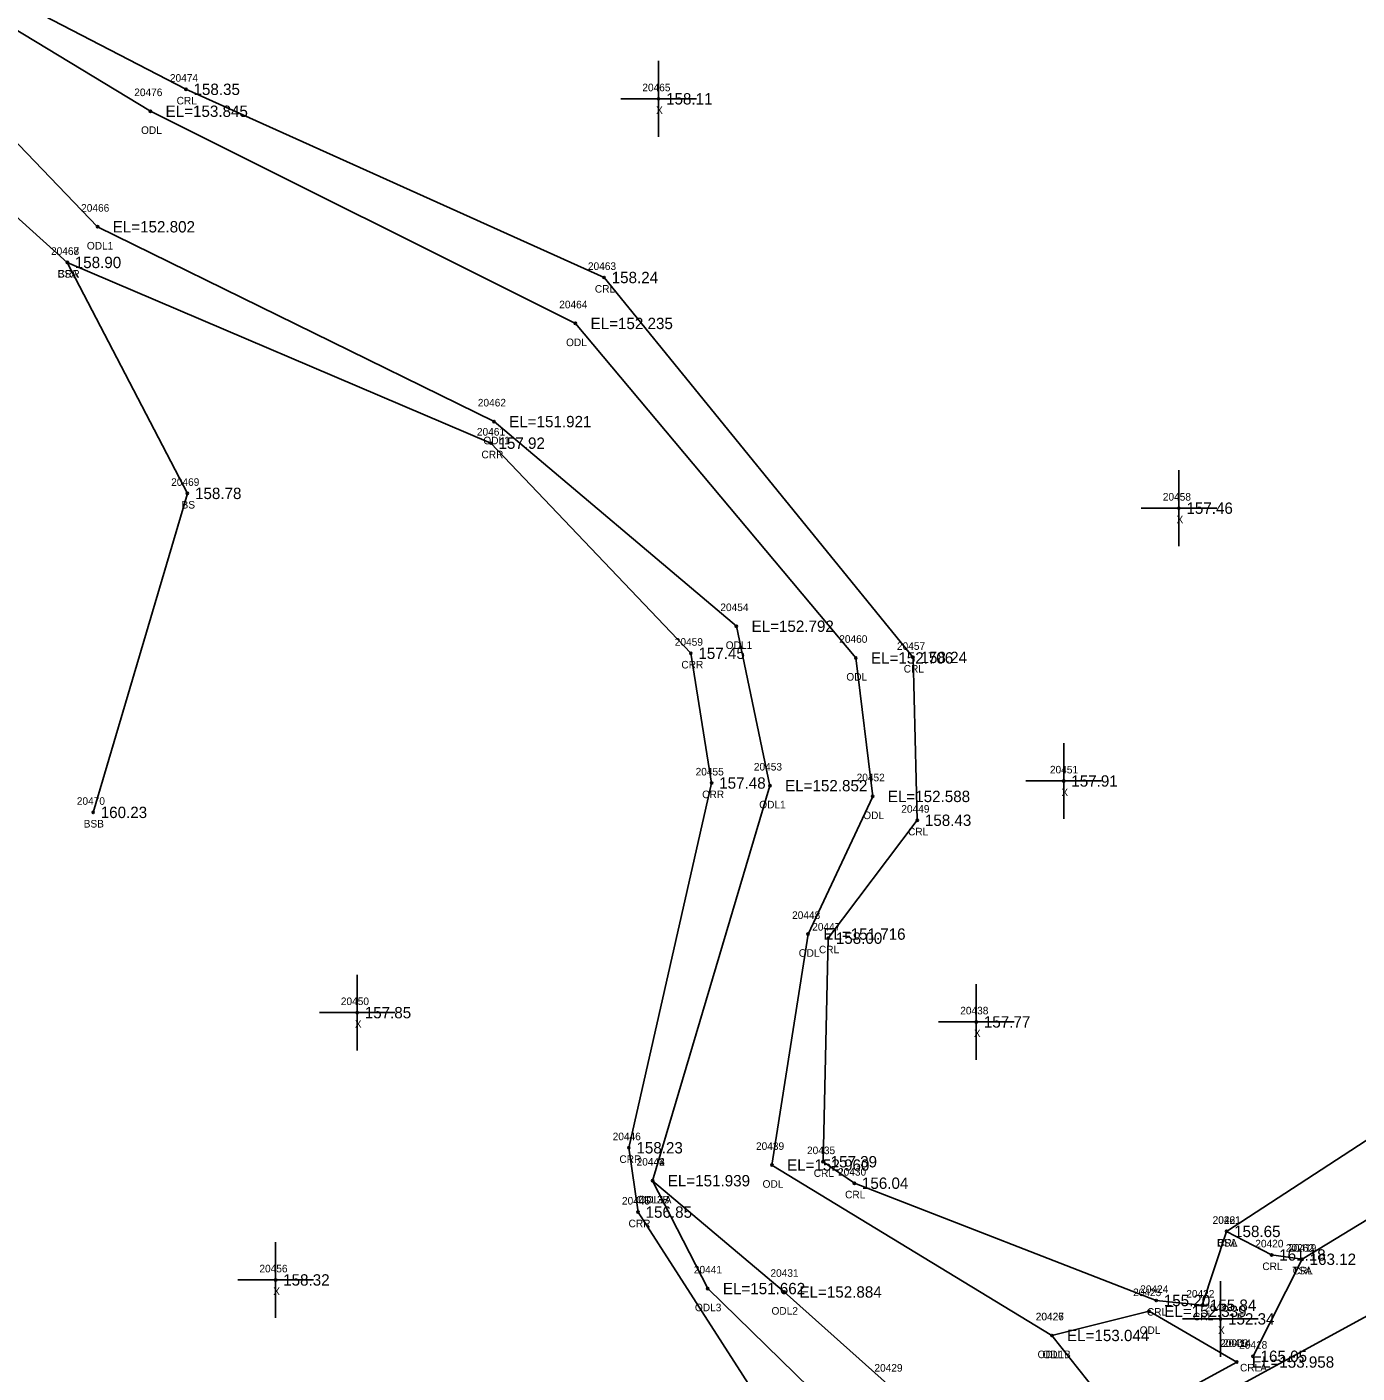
# Model space of a CAD drawing. Extents: x 2279528 to 2280976, y 1061373 to 1062235.
# Drawn here: x 2280085.6 to 2280261.4, y 1061818 to 1061995.9 of the extents above; entities that cross this region are included whole.
import ezdxf

# ---------------------------------------------------------------- set-up
doc = ezdxf.new("R2010")
doc.units = 0
for name, color, linetype in [('RD_DTM_BkLn2', 7, 'Continuous'), ('RD_DTM_BkLn_txCode', 7, 'Continuous'), ('RD_EX_H2O', 7, 'Continuous'), ('RD_EX_H2O_txCode', 7, 'Continuous'), ('RD_EX_Misc', 7, 'Continuous'), ('RD_EX_Misc_txCode', 7, 'Continuous'), ('RD_EX_Road', 7, 'Continuous'), ('RD_EX_TX_H2O_ELEV', 7, 'Continuous'), ('RD_EX_TX_Misc_ELEV', 7, 'Continuous'), ('RD_SMD_Locator', 7, 'Continuous')]:
    doc.layers.add(name, color=color, linetype=linetype)

msp = doc.modelspace()

# ---------------------------------------------------------------- linework, layer by layer
at = {"layer": 'RD_DTM_BkLn2'}
for points in [[(2280244.17, 1061836.72), (2280279.92, 1061859.99), (2280384.06, 1061910.85), (2280474.95, 1061958.02), (2280563.04, 1062001.93), (2280638.18, 1062044.64), (2280638.45, 1062052), (2280636.3, 1062090.14)], [(2280254.15, 1061833.04), (2280297.35, 1061859.31), (2280389.94, 1061901.4), (2280479.75, 1061950.78), (2280565.23, 1061997.82), (2280647.02, 1062043.23), (2280646.04, 1062059.26), (2280636.3, 1062090.14)], [(2280090.97, 1061964.76), (2280106.86, 1061934.24), (2280094.4, 1061892.09)]]:
    msp.add_lwpolyline(points, dxfattribs=at)
at = {"layer": 'RD_EX_H2O'}
msp.add_line((2280230.44, 1061811.21), (2280221.09, 1061822.97), dxfattribs=at)
for points in [[(2280211.16, 1061800.79), (2280200.18, 1061802.95), (2280195.55, 1061801.16), (2280185.62, 1061809.36), (2280166.4, 1061839.27), (2280165.19, 1061847.77), (2280176.13, 1061895.97), (2280173.38, 1061913.11), (2280146.96, 1061940.88), (2280090.97, 1061964.76), (2280049.27, 1062002.4), (2280058.65, 1062048.88), (2280050.78, 1062064.28), (2280035.9, 1062083.09), (2280001.73, 1062095.49), (2279975.65, 1062129.45), (2279976.82, 1062173.44)], [(2280168.33, 1061843.42), (2280183.83, 1061895.62), (2280179.4, 1061916.69), (2280147.37, 1061943.73), (2280094.98, 1061969.47), (2280057.58, 1062008.45), (2280067.95, 1062052.6), (2280055.34, 1062070.59), (2280037.3, 1062087.39), (2280003.55, 1062098.15), (2279979.87, 1062130.72), (2279980.65, 1062169.39)], [(2280245.52, 1061819.46), (2280233.94, 1061826.17), (2280221.09, 1061822.97), (2280184.1, 1061845.49), (2280188.88, 1061876.01), (2280197.41, 1061894.2), (2280195.18, 1061912.5), (2280158.13, 1061956.7), (2280101.97, 1061984.74), (2280076.14, 1062000.42), (2280073.45, 1062020.04), (2280088.34, 1062054.57), (2280063.06, 1062089.79), (2280022.01, 1062117.09), (2280004.42, 1062121.87), (2279996.3, 1062161.48)], [(2280247.67, 1061820.22), (2280254.15, 1061833.04), (2280250.13, 1061833.61), (2280244.17, 1061836.72), (2280240.97, 1061826.97), (2280234.88, 1061827.59), (2280194.99, 1061843.09), (2280190.85, 1061845.93), (2280191.54, 1061875.47), (2280203.31, 1061891.05), (2280202.74, 1061912.57), (2280161.92, 1061962.77), (2280106.66, 1061987.64), (2280081.48, 1062000.69), (2280077.59, 1062019.21), (2280091.23, 1062055.4), (2280068.77, 1062094.03), (2280025.87, 1062122.57), (2280008.58, 1062126.75), (2280003.39, 1062153.96)], [(2280211.72, 1061801.11), (2280200.63, 1061804.74), (2280175.61, 1061829.17), (2280168.33, 1061843.42)], [(2280227.06, 1061809.78), (2280213.62, 1061812.44), (2280199.76, 1061816.19), (2280185.73, 1061828.72), (2280168.33, 1061843.42)], [(2280211.72, 1061801.11), (2280227.06, 1061809.78), (2280230.44, 1061811.21), (2280245.52, 1061819.46)]]:
    msp.add_lwpolyline(points, dxfattribs=at)
at = {"layer": 'RD_EX_Misc'}
for p, q in [((2280169.11, 1061981.38), (2280169.11, 1061991.38)), ((2280164.11, 1061986.38), (2280174.11, 1061986.38)), ((2280237.87, 1061927.29), (2280237.87, 1061937.29)), ((2280232.87, 1061932.29), (2280242.87, 1061932.29)), ((2280222.66, 1061891.24), (2280222.66, 1061901.24)), ((2280217.66, 1061896.24), (2280227.66, 1061896.24)), ((2280129.29, 1061860.63), (2280129.29, 1061870.63)), ((2280211.1, 1061859.4), (2280211.1, 1061869.4)), ((2280124.29, 1061865.63), (2280134.29, 1061865.63)), ((2280206.1, 1061864.4), (2280216.1, 1061864.4)), ((2280118.51, 1061825.31), (2280118.51, 1061835.31)), ((2280113.51, 1061830.31), (2280123.51, 1061830.31)), ((2280243.37, 1061820.16), (2280243.37, 1061830.16)), ((2280238.37, 1061825.16), (2280248.37, 1061825.16))]:
    msp.add_line(p, q, dxfattribs=at)
at = {"layer": 'RD_EX_Road'}
msp.add_lwpolyline([(2279554.31, 1061441.46), (2279636.61, 1061486.51), (2279673.46, 1061506.76), (2279683.06, 1061512.21), (2279723.14, 1061533.54), (2279809.28, 1061580.29), (2279896.91, 1061627.91), (2279977.07, 1061671.02), (2280059.64, 1061715.57), (2280142.91, 1061760.72), (2280228.83, 1061807.06), (2280306.04, 1061849.18), (2280392.98, 1061896.71), (2280482.82, 1061945.75), (2280567.83, 1061991.78), (2280649.94, 1062036.55), (2280660.56, 1062042.19), (2280676.12, 1062050.66), (2280737.28, 1062083.64), (2280828.54, 1062132.77), (2280887.86, 1062164.61), (2280934.91, 1062190.9)], dxfattribs=at)
at = {"layer": 'RD_SMD_Locator'}
for centre in [(2280106.66, 1061987.64), (2280101.97, 1061984.74), (2280169.11, 1061986.38), (2280094.98, 1061969.47), (2280090.97, 1061964.76), (2280090.97, 1061964.76), (2280161.92, 1061962.77), (2280158.13, 1061956.7), (2280147.37, 1061943.73), (2280146.96, 1061940.88), (2280106.86, 1061934.24), (2280237.87, 1061932.29), (2280179.4, 1061916.69), (2280173.38, 1061913.11), (2280195.18, 1061912.5), (2280202.74, 1061912.57), (2280176.13, 1061895.97), (2280222.66, 1061896.24), (2280183.83, 1061895.62), (2280197.41, 1061894.2), (2280094.4, 1061892.09), (2280203.31, 1061891.05), (2280188.88, 1061876.01), (2280191.54, 1061875.47), (2280129.29, 1061865.63), (2280211.1, 1061864.4), (2280165.19, 1061847.77), (2280184.1, 1061845.49), (2280190.85, 1061845.93), (2280168.33, 1061843.42), (2280168.33, 1061843.42), (2280168.33, 1061843.42), (2280194.99, 1061843.09), (2280166.4, 1061839.27), (2280244.17, 1061836.72), (2280244.17, 1061836.72), (2280250.13, 1061833.61), (2280254.15, 1061833.04), (2280254.15, 1061833.04), (2280118.51, 1061830.31), (2280175.61, 1061829.17), (2280185.73, 1061828.72), (2280234.88, 1061827.59), (2280240.97, 1061826.97), (2280233.94, 1061826.17), (2280243.37, 1061825.16), (2280221.09, 1061822.97), (2280221.09, 1061822.97), (2280245.52, 1061819.46), (2280245.52, 1061819.46), (2280247.67, 1061820.22)]:
    msp.add_circle(centre, 0.15, dxfattribs=at)

# ---------------------------------------------------------------- texts
at = {"layer": 'RD_DTM_BkLn_txCode'}
for s, p in [('20468', (2280088.83, 1061965.76)), ('BSA', (2280089.71, 1061962.76)), ('20469', (2280104.71, 1061935.24)), ('BS', (2280106.08, 1061932.24)), ('20470', (2280092.24, 1061893.09)), ('BSB', (2280093.15, 1061890.09)), ('20261', (2280242.32, 1061837.72)), ('BSA', (2280242.91, 1061834.72)), ('20262', (2280252.01, 1061834.04)), ('TSA', (2280252.87, 1061831.04))]:
    msp.add_text(s, height=1, dxfattribs=at).set_placement(p)
at = {"layer": 'RD_EX_H2O_txCode'}
for s, p in [('20474', (2280104.54, 1061988.64)), ('20476', (2280099.83, 1061986.74)), ('CRL', (2280105.43, 1061985.64)), ('ODL', (2280100.73, 1061981.74)), ('20466', (2280092.81, 1061971.47)), ('ODL1', (2280093.57, 1061966.47)), ('20467', (2280088.83, 1061965.76)), ('CRR', (2280089.72, 1061962.76)), ('20463', (2280159.78, 1061963.77)), ('CRL', (2280160.7, 1061960.77)), ('20464', (2280155.99, 1061958.7)), ('ODL', (2280156.89, 1061953.7)), ('20462', (2280145.23, 1061945.73)), ('20461', (2280145.11, 1061941.88)), ('ODL1', (2280145.96, 1061940.73)), ('CRR', (2280145.71, 1061938.88)), ('20454', (2280177.28, 1061918.69)), ('20460', (2280192.99, 1061914.5)), ('20459', (2280171.26, 1061914.11)), ('ODL1', (2280177.99, 1061913.69)), ('20457', (2280200.62, 1061913.57)), ('CRR', (2280172.13, 1061911.11)), ('ODL', (2280193.93, 1061909.5)), ('CRL', (2280201.51, 1061910.57)), ('20455', (2280174.01, 1061896.97)), ('20453', (2280181.71, 1061897.62)), ('20452', (2280195.29, 1061896.2)), ('CRR', (2280174.88, 1061893.97)), ('ODL1', (2280182.42, 1061892.62)), ('20449', (2280201.19, 1061892.05)), ('ODL', (2280196.16, 1061891.2)), ('CRL', (2280202.08, 1061889.05)), ('20448', (2280186.76, 1061878.01)), ('20447', (2280189.42, 1061876.47)), ('ODL', (2280187.64, 1061873.01)), ('CRL', (2280190.31, 1061873.47)), ('20446', (2280163.05, 1061848.77)), ('20439', (2280181.99, 1061847.49)), ('20435', (2280188.73, 1061846.93)), ('CRR', (2280163.94, 1061845.77)), ('20442', (2280166.21, 1061845.42)), ('20443', (2280166.21, 1061845.42)), ('20444', (2280166.21, 1061845.42)), ('CRL', (2280189.62, 1061843.93)), ('20430', (2280192.83, 1061844.09)), ('ODL', (2280182.86, 1061842.49)), ('20445', (2280164.28, 1061840.27)), ('ODL3B', (2280166.16, 1061840.42)), ('ODL2B', (2280166.16, 1061840.42)), ('ODL1A', (2280166.43, 1061840.42)), ('CRL', (2280193.76, 1061841.09)), ('CRR', (2280165.15, 1061837.27)), ('20421', (2280242.34, 1061837.72)), ('CRL', (2280242.95, 1061834.72)), ('20420', (2280247.97, 1061834.61)), ('20419', (2280252.32, 1061834.04)), ('20441', (2280173.78, 1061831.17)), ('CRL', (2280248.9, 1061831.61)), ('CRL', (2280252.92, 1061831.04)), ('20431', (2280183.9, 1061830.72)), ('20425', (2280231.82, 1061828.17)), ('20424', (2280232.76, 1061828.59)), ('20422', (2280238.85, 1061827.97)), ('ODL3', (2280173.92, 1061826.17)), ('ODL2', (2280184.04, 1061825.72)), ('CRL', (2280233.65, 1061825.59)), ('20426', (2280218.95, 1061824.97)), ('20427', (2280218.97, 1061824.97)), ('CRL', (2280239.74, 1061824.97)), ('ODL', (2280232.69, 1061823.17)), ('20003', (2280243.32, 1061821.46)), ('20414', (2280243.69, 1061821.46)), ('20418', (2280245.83, 1061821.22)), ('ODL1B', (2280219.2, 1061819.97)), ('ODL', (2280219.84, 1061819.97)), ('20429', (2280197.64, 1061818.19)), ('CRLA', (2280245.95, 1061818.22))]:
    msp.add_text(s, height=1, dxfattribs=at).set_placement(p)
at = {"layer": 'RD_EX_Misc_txCode'}
for s, p in [('20465', (2280166.97, 1061987.38)), ('X', (2280168.79, 1061984.38)), ('20458', (2280235.75, 1061933.29)), ('X', (2280237.56, 1061930.29)), ('20451', (2280220.83, 1061897.24)), ('X', (2280222.35, 1061894.24)), ('20450', (2280127.13, 1061866.63)), ('20438', (2280208.98, 1061865.4)), ('X', (2280128.98, 1061863.63)), ('X', (2280210.78, 1061862.4)), ('20456', (2280116.37, 1061831.31)), ('X', (2280118.19, 1061828.31)), ('20423', (2280241.25, 1061826.16)), ('X', (2280243.05, 1061823.16))]:
    msp.add_text(s, height=1, dxfattribs=at).set_placement(p)
at = {"layer": 'RD_EX_TX_H2O_ELEV'}
for s, p in [('158.35', (2280107.66, 1061986.89)), ('EL=153.845', (2280103.97, 1061983.99)), ('EL=152.802', (2280096.98, 1061968.72)), ('158.90', (2280091.97, 1061964.01)), ('158.24', (2280162.92, 1061962.02)), ('EL=152.235', (2280160.13, 1061955.95)), ('EL=151.921', (2280149.37, 1061942.98)), ('157.92', (2280147.96, 1061940.13)), ('EL=152.792', (2280181.4, 1061915.94)), ('157.45', (2280174.38, 1061912.36)), ('EL=152.706', (2280197.18, 1061911.75)), ('158.24', (2280203.74, 1061911.82)), ('157.48', (2280177.13, 1061895.22)), ('EL=152.852', (2280185.83, 1061894.87)), ('EL=152.588', (2280199.41, 1061893.45)), ('158.43', (2280204.31, 1061890.3)), ('EL=151.716', (2280190.88, 1061875.26)), ('158.00', (2280192.54, 1061874.72)), ('158.23', (2280166.19, 1061847.02)), ('EL=152.960', (2280186.1, 1061844.74)), ('157.39', (2280191.85, 1061845.18)), ('EL=151.939', (2280170.33, 1061842.67)), ('EL=151.939', (2280170.33, 1061842.67)), ('EL=151.939', (2280170.33, 1061842.67)), ('156.04', (2280195.99, 1061842.34)), ('156.85', (2280167.4, 1061838.52)), ('158.65', (2280245.17, 1061835.97)), ('161.18', (2280251.13, 1061832.86)), ('163.12', (2280255.15, 1061832.29)), ('EL=151.662', (2280177.61, 1061828.42)), ('EL=152.884', (2280187.73, 1061827.97)), ('155.20', (2280235.88, 1061826.84)), ('EL=152.339', (2280235.94, 1061825.42)), ('155.84', (2280241.97, 1061826.22)), ('EL=153.044', (2280223.09, 1061822.22)), ('EL=153.044', (2280223.09, 1061822.22)), ('EL=153.958', (2280247.52, 1061818.71)), ('EL=153.958', (2280247.52, 1061818.71)), ('165.05', (2280248.67, 1061819.47))]:
    msp.add_text(s, height=1.5, dxfattribs=at).set_placement(p)
at = {"layer": 'RD_EX_TX_Misc_ELEV'}
for s, p in [('158.11', (2280170.11, 1061985.63)), ('158.90', (2280091.97, 1061964.01)), ('158.78', (2280107.86, 1061933.49)), ('157.46', (2280238.87, 1061931.54)), ('157.91', (2280223.66, 1061895.49)), ('160.23', (2280095.4, 1061891.34)), ('157.85', (2280130.29, 1061864.88)), ('157.77', (2280212.1, 1061863.65)), ('158.65', (2280245.17, 1061835.97)), ('163.12', (2280255.15, 1061832.29)), ('158.32', (2280119.51, 1061829.56)), ('152.34', (2280244.37, 1061824.41))]:
    msp.add_text(s, height=1.5, dxfattribs=at).set_placement(p)

doc.saveas('drawing.dxf')
